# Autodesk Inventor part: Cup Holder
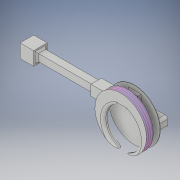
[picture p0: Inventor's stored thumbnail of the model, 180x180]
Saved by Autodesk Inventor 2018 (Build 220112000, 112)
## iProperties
Created: 2017-07
Part Number: Cup Holder
Material: Generic
Document SubType Name: Modeling
Designer: 17046589
Density: 1 g/cm^3
Appearance: Default
Author: 17046589
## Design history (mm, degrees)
sketch "Sketch1"
  geometry: L1 (0, 0)-(-10, 0); L2 (-10, 0)-(-10, -10); L3 (-10, -10)-(0, -10); L4 (0, -10)-(0, 0)
  constraints: 8 end point, 2 perpendicular, 1 horizontal, 1 vertical
  dimensions: "d0" = 10 distance of L1.start L1.end; "d1" = 10 distance of L1.end L2.end
extrude "Extrusion1" new body sketch "Sketch1" distance "d2" = 10; taper "d3" = 0 deg
sketch "Sketch2"
  geometry: L1 (2.358, 7.658)-(7.588, 7.658); L2 (7.588, 7.658)-(7.588, 2.475); L3 (7.588, 2.475)-(2.358, 2.475); L4 (2.358, 2.475)-(2.358, 7.658); 1 further point
  constraints: 8 end point, 2 parallel, 1 horizontal, 1 perpendicular
extrude "Extrusion2" join sketch "Sketch2" distance "d4" = 40; taper "d5" = 0 deg
sketch "Sketch3"
  geometry: L1 (1.051, 8.685)-(8.849, 8.685); L2 (8.849, 8.685)-(8.849, 1.027); L3 (8.849, 1.027)-(1.051, 1.027); L4 (1.051, 1.027)-(1.051, 8.685); 1 further point
  constraints: 8 end point, 2 parallel, 1 horizontal, 1 perpendicular
extrude "Extrusion3" join sketch "Sketch3" distance "d6" = 50; taper "d7" = 0 deg
sketch "Sketch4"
  geometry: C1 r 18.982 at (33.452, 4.289); 1 further point
  constraints: 1 centre point
extrude "Extrusion4" join sketch "Sketch4" distance "d8" = 0.3; taper "d9" = 0 deg
chamfer "Chamfer1" distance "d10" = 1.25; stored, may be unused: second distance "d11" = 1.25, angle "d12" = 45 deg
chamfer "Chamfer2" distance "d13" = 1.25; stored, may be unused: second distance "d14" = 1.25, angle "d15" = 45 deg
chamfer "Chamfer3" distance "d16" = 1.25; stored, may be unused: second distance "d17" = 1.25, angle "d18" = 45 deg
fillet "Fillet1" dims "d19" = 2
chamfer "Chamfer4" distance "d20" = 1.25; stored, may be unused: second distance "d21" = 1.25, angle "d22" = 45 deg
sketch "Sketch5"
  geometry: L1 (-3.03, 14.548)-(3.937, 14.548); L2 (3.937, 14.548)-(3.937, 9.656); L3 (3.937, 9.656)-(-3.03, 9.656); L4 (-3.03, 9.656)-(-3.03, 14.548); 1 further point
  constraints: 8 end point, 2 parallel, 1 horizontal, 1 perpendicular
extrude "Extrusion5" join sketch "Sketch5" distance "d23" = 5; taper "d24" = 0 deg
sketch "Sketch6"
  geometry: C1 r 18.982 at (0, 0); 1 further point
  constraints: 1 centre point
extrude "Extrusion6" join sketch "Sketch6" distance "d25" = 5; taper "d26" = 0 deg
sketch "Sketch7"
  geometry: L1 (-3.03, 9.656)-(-3.03, 14.548) reference; L2 (-3.03, 9.656)-(3.297, 9.656); L3 (3.297, 9.656)-(3.297, -20.173); L4 (3.297, -20.173)-(-3.03, -20.173); L5 (-3.03, -20.173)-(-3.03, 9.656); 1 further point
  constraints: 8 end point, 2 parallel, 1 horizontal, 1 perpendicular
extrude "Extrusion7" cut sketch "Sketch7" distance "d27" = 5; taper "d28" = 0 deg
sketch "Sketch8"
  geometry: L1 (3.937, 9.656)-(-3.03, 9.656) reference; L2 (-3.03, 9.656)-(-3.03, -18.739); L3 (3.297, -18.694)-(3.297, 9.656) reference; L4 (3.297, 9.656)-(3.297, -18.694); A1 r 15.144 centre (2.239, -4.541) between (-3.03, 9.656) and (-3.03, -18.739); A2 r 15.14 centre (-1.691, -4.399) between (3.297, -18.694) and (3.937, 9.656); 1 further point
  constraints: 4 end point, 4 point on circle, 2 centre point, 1 collinear, 1 vertical
  dimensions: "d29" = 15.14 radius of A2
extrude "Extrusion8" cut sketch "Sketch8" distance "d30" = 5; taper "d31" = 0 deg
fillet "Fillet2" dims "d32" = 2
chamfer "Chamfer5" distance "d33" = 1.25; stored, may be unused: second distance "d34" = 1.25, angle "d35" = 45 deg
thread "Thread1" dims "d36" = 10, "d37" = 0
chamfer "Chamfer6" distance "d38" = 1.25; stored, may be unused: second distance "d39" = 1.25, angle "d40" = 45 deg
body "Solid1"
